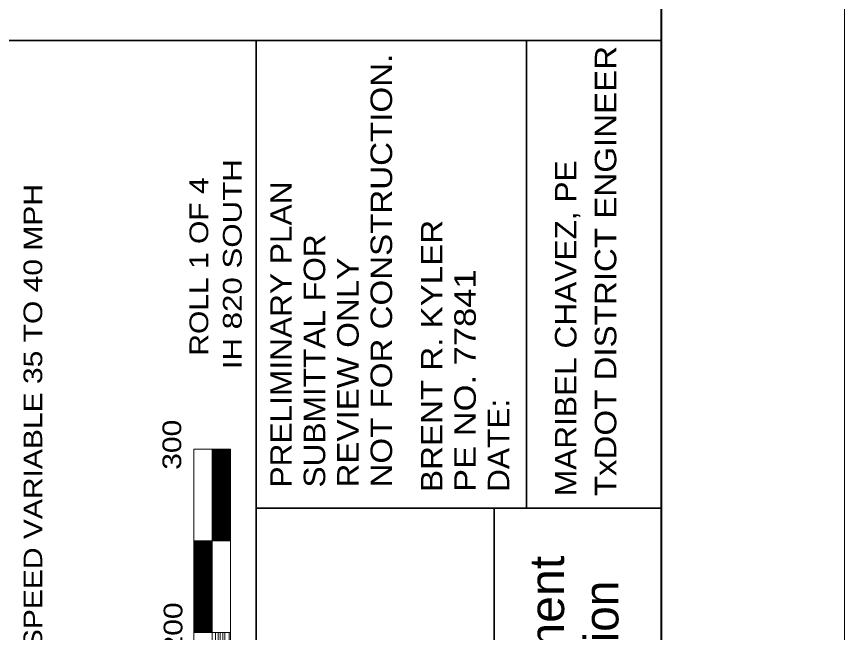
# Model space of a CAD drawing. Extents: x 2363323 to 2367082, y 6956018 to 6980837.
# Drawn here: x 2366471.6 to 2366923.3, y 6957628.9 to 6957965 of the extents above; entities that cross this region are included whole.
import ezdxf
from ezdxf.enums import TextEntityAlignment as Align

# ---------------------------------------------------------------- set-up
doc = ezdxf.new("R2010")
doc.units = 0
doc.header["$LTSCALE"] = 4.1
doc.layers.add('62', color=7, linetype='Continuous', lineweight=13)
doc.layers.add('63', color=7, linetype='Continuous', lineweight=13)

msp = doc.modelspace()

# ---------------------------------------------------------------- linework, layer by layer
at = {"layer": '62'}
for p, q in [((2366923.344, 6980256.082), (2366923.344, 6957200.912)), ((2366568.268, 6957328.893), (2366568.268, 6957728.93)), ((2366568.268, 6957728.93), (2366578.269, 6957728.93)), ((2366578.269, 6957328.894), (2366578.269, 6957728.93)), ((2366578.269, 6957728.93), (2366588.27, 6957728.93)), ((2366578.536, 6957678.925), (2366578.537, 6957728.929)), ((2366579.036, 6957678.925), (2366579.036, 6957728.929)), ((2366579.536, 6957678.924), (2366579.536, 6957728.93)), ((2366580.036, 6957678.924), (2366580.037, 6957728.929)), ((2366580.535, 6957678.924), (2366580.536, 6957728.929)), ((2366581.036, 6957678.924), (2366581.036, 6957728.929)), ((2366581.536, 6957678.924), (2366581.535, 6957728.929)), ((2366582.036, 6957678.924), (2366582.035, 6957728.93)), ((2366582.536, 6957678.925), (2366582.536, 6957728.929)), ((2366583.036, 6957678.925), (2366583.035, 6957728.929)), ((2366583.536, 6957678.925), (2366583.536, 6957728.93)), ((2366584.036, 6957678.925), (2366584.036, 6957728.93)), ((2366584.536, 6957678.923), (2366584.536, 6957728.93)), ((2366585.036, 6957678.924), (2366585.036, 6957728.929)), ((2366585.537, 6957678.924), (2366585.536, 6957728.929)), ((2366586.037, 6957678.924), (2366586.037, 6957728.929)), ((2366586.537, 6957678.924), (2366586.537, 6957728.929)), ((2366587.037, 6957678.924), (2366587.037, 6957728.93)), ((2366587.537, 6957678.925), (2366587.537, 6957728.929)), ((2366588.037, 6957678.925), (2366588.037, 6957728.93)), ((2366588.269, 6957328.893), (2366588.27, 6957728.93)), ((2366568.268, 6957678.924), (2366578.268, 6957678.924)), ((2366568.659, 6957628.921), (2366568.659, 6957678.924)), ((2366569.16, 6957628.921), (2366569.16, 6957678.925)), ((2366569.66, 6957628.921), (2366569.66, 6957678.924)), ((2366570.159, 6957628.92), (2366570.16, 6957678.925)), ((2366570.659, 6957628.92), (2366570.661, 6957678.924)), ((2366571.16, 6957628.92), (2366571.16, 6957678.924)), ((2366571.66, 6957628.921), (2366571.66, 6957678.925)), ((2366572.16, 6957628.92), (2366572.16, 6957678.924)), ((2366572.66, 6957628.92), (2366572.66, 6957678.924)), ((2366573.16, 6957628.921), (2366573.161, 6957678.924)), ((2366573.66, 6957628.92), (2366573.661, 6957678.925)), ((2366574.16, 6957628.921), (2366574.16, 6957678.925)), ((2366574.66, 6957628.92), (2366574.66, 6957678.924)), ((2366575.16, 6957628.921), (2366575.159, 6957678.924)), ((2366575.66, 6957628.92), (2366575.66, 6957678.924)), ((2366576.16, 6957628.92), (2366576.16, 6957678.925)), ((2366576.66, 6957628.921), (2366576.659, 6957678.925)), ((2366577.16, 6957628.92), (2366577.16, 6957678.924)), ((2366577.66, 6957628.921), (2366577.66, 6957678.925)), ((2366578.16, 6957628.921), (2366578.16, 6957678.924)), ((2366578.268, 6957678.924), (2366588.27, 6957678.924)), ((2366568.268, 6957628.921), (2366578.269, 6957628.921)), ((2366578.269, 6957628.921), (2366588.269, 6957628.92)), ((2366580.16, 6957578.915), (2366580.16, 6957628.921)), ((2366581.66, 6957578.915), (2366581.659, 6957628.921)), ((2366582.66, 6957578.915), (2366582.659, 6957628.921)), ((2366584.16, 6957578.916), (2366584.159, 6957628.921)), ((2366585.162, 6957578.916), (2366585.161, 6957628.921)), ((2366587.661, 6957578.916), (2366587.661, 6957628.921))]:
    msp.add_line(p, q, dxfattribs=at)
at = {"layer": '62', "lineweight": 40}
msp.add_line((2366823.34, 6980156.078), (2366823.34, 6957300.912), dxfattribs=at)
at = {"layer": '62', "lineweight": 35}
for p, q in [((2366226.481, 6957951.933), (2366823.339, 6957951.933)), ((2366602.353, 6957951.933), (2366602.354, 6957300.911)), ((2366749.892, 6957951.933), (2366749.892, 6957696.747)), ((2366823.338, 6957696.748), (2366602.353, 6957696.746)), ((2366732.124, 6957696.747), (2366732.124, 6957300.911))]:
    msp.add_line(p, q, dxfattribs=at)
at = {"layer": '62'}
for points in [[(2366588.27, 6957678.924), (2366588.27, 6957728.93), (2366578.269, 6957728.93), (2366578.268, 6957678.924)], [(2366578.269, 6957628.921), (2366578.268, 6957678.924), (2366568.268, 6957678.924), (2366568.268, 6957628.921)], [(2366588.27, 6957578.915), (2366588.269, 6957628.92), (2366578.269, 6957628.921), (2366578.269, 6957578.915)]]:
    msp.add_lwpolyline(points, close=True, dxfattribs=at)
at = {"layer": '63'}
for p, q in [((2366923.344, 6980256.082), (2366923.344, 6957200.912)), ((2366568.268, 6957328.893), (2366568.268, 6957728.93)), ((2366568.268, 6957728.93), (2366578.269, 6957728.93)), ((2366578.269, 6957328.894), (2366578.269, 6957728.93)), ((2366578.269, 6957728.93), (2366588.27, 6957728.93)), ((2366578.536, 6957678.925), (2366578.537, 6957728.929)), ((2366579.036, 6957678.925), (2366579.036, 6957728.929)), ((2366579.536, 6957678.924), (2366579.536, 6957728.93)), ((2366580.036, 6957678.924), (2366580.037, 6957728.929)), ((2366580.535, 6957678.924), (2366580.536, 6957728.929)), ((2366581.036, 6957678.924), (2366581.036, 6957728.929)), ((2366581.536, 6957678.924), (2366581.535, 6957728.929)), ((2366582.036, 6957678.924), (2366582.035, 6957728.93)), ((2366582.536, 6957678.925), (2366582.536, 6957728.929)), ((2366583.036, 6957678.925), (2366583.035, 6957728.929)), ((2366583.536, 6957678.925), (2366583.536, 6957728.93)), ((2366584.036, 6957678.925), (2366584.036, 6957728.93)), ((2366584.536, 6957678.923), (2366584.536, 6957728.93)), ((2366585.036, 6957678.924), (2366585.036, 6957728.929)), ((2366585.537, 6957678.924), (2366585.536, 6957728.929)), ((2366586.037, 6957678.924), (2366586.037, 6957728.929)), ((2366586.537, 6957678.924), (2366586.537, 6957728.929)), ((2366587.037, 6957678.924), (2366587.037, 6957728.93)), ((2366587.537, 6957678.925), (2366587.537, 6957728.929)), ((2366588.037, 6957678.925), (2366588.037, 6957728.93)), ((2366588.269, 6957328.893), (2366588.27, 6957728.93)), ((2366568.268, 6957678.924), (2366578.268, 6957678.924)), ((2366568.659, 6957628.921), (2366568.659, 6957678.924)), ((2366569.16, 6957628.921), (2366569.16, 6957678.925)), ((2366569.66, 6957628.921), (2366569.66, 6957678.924)), ((2366570.159, 6957628.92), (2366570.16, 6957678.925)), ((2366570.659, 6957628.92), (2366570.661, 6957678.924)), ((2366571.16, 6957628.92), (2366571.16, 6957678.924)), ((2366571.66, 6957628.921), (2366571.66, 6957678.925)), ((2366572.16, 6957628.92), (2366572.16, 6957678.924)), ((2366572.66, 6957628.92), (2366572.66, 6957678.924)), ((2366573.16, 6957628.921), (2366573.161, 6957678.924)), ((2366573.66, 6957628.92), (2366573.661, 6957678.925)), ((2366574.16, 6957628.921), (2366574.16, 6957678.925)), ((2366574.66, 6957628.92), (2366574.66, 6957678.924)), ((2366575.16, 6957628.921), (2366575.159, 6957678.924)), ((2366575.66, 6957628.92), (2366575.66, 6957678.924)), ((2366576.16, 6957628.92), (2366576.16, 6957678.925)), ((2366576.66, 6957628.921), (2366576.659, 6957678.925)), ((2366577.16, 6957628.92), (2366577.16, 6957678.924)), ((2366577.66, 6957628.921), (2366577.66, 6957678.925)), ((2366578.16, 6957628.921), (2366578.16, 6957678.924)), ((2366578.268, 6957678.924), (2366588.27, 6957678.924)), ((2366568.268, 6957628.921), (2366578.269, 6957628.921)), ((2366578.269, 6957628.921), (2366588.269, 6957628.92)), ((2366580.16, 6957578.915), (2366580.16, 6957628.921)), ((2366581.66, 6957578.915), (2366581.659, 6957628.921)), ((2366582.66, 6957578.915), (2366582.659, 6957628.921)), ((2366584.16, 6957578.916), (2366584.159, 6957628.921)), ((2366585.162, 6957578.916), (2366585.161, 6957628.921)), ((2366587.661, 6957578.916), (2366587.661, 6957628.921))]:
    msp.add_line(p, q, dxfattribs=at)
at = {"layer": '63', "lineweight": 40}
msp.add_line((2366823.34, 6980156.078), (2366823.34, 6957300.912), dxfattribs=at)
at = {"layer": '63', "lineweight": 35}
for p, q in [((2366226.481, 6957951.933), (2366823.339, 6957951.933)), ((2366602.353, 6957951.933), (2366602.354, 6957300.911)), ((2366749.892, 6957951.933), (2366749.892, 6957696.316)), ((2366823.338, 6957696.748), (2366602.353, 6957696.746))]:
    msp.add_line(p, q, dxfattribs=at)
at = {"layer": '63'}
for points in [[(2366588.27, 6957678.924), (2366588.27, 6957728.93), (2366578.269, 6957728.93), (2366578.268, 6957678.924)], [(2366578.269, 6957628.921), (2366578.268, 6957678.924), (2366568.268, 6957678.924), (2366568.268, 6957628.921)], [(2366588.27, 6957578.915), (2366588.269, 6957628.92), (2366578.269, 6957628.921), (2366578.269, 6957578.915)]]:
    msp.add_lwpolyline(points, close=True, dxfattribs=at)

# ---------------------------------------------------------------- texts
at = {"layer": '62'}
for s, width, p in [('TxDOT DISTRICT ENGINEER', 1.15, (2366798.864, 6957703.252)), ('NOT FOR CONSTRUCTION.', 1.15, (2366676.499, 6957708.016)), ('MARIBEL CHAVEZ, PE', 1.1, (2366777.125, 6957703.251)), ('PRELIMINARY PLAN', 1.1, (2366621.773, 6957708.015)), ('BRENT R. KYLER', 1.15, (2366703.962, 6957705.575)), ('SUBMITTAL FOR', 1.1, (2366640.015, 6957708.016)), ('REVIEW ONLY', 1.15, (2366658.257, 6957708.016)), ('PE NO. 77841', 1.2, (2366722.199, 6957705.575)), ('DATE: ', 1.1, (2366740.434, 6957705.576))]:
    msp.add_text(s, height=11.74, rotation=90, dxfattribs=dict(at, width=width)).set_placement(p)
for s, height, width, p in [('IH 820 SOUTH', 10.2, 1.25, (2366594.414, 6957829.863)), ('ROLL 1 OF 4', 10.2, 1.2, (2366576.159, 6957828.614)), ('FRONTAGE ROAD DESIGN SPEED VARIABLE 35 TO 40 MPH', 10.2, 1.2, (2366485.591, 6957639.41)), ('300', 10.2, 1.2, (2366561.427, 6957731.346)), ('Texas Department', 18.76, 1.05, (2366770.36, 6957562.432)), ('200', 10.2, 1.2, (2366562.077, 6957631.661))]:
    msp.add_text(s, height=height, rotation=90, dxfattribs=dict(at, width=width)).set_placement(p, align=Align.CENTER)
msp.add_text('of Transportation', height=18.76, rotation=90, dxfattribs=at).set_placement((2366800.012, 6957562.362), align=Align.CENTER)
at = {"layer": '63'}
for s, width, p in [('NOT FOR CONSTRUCTION.', 1.15, (2366676.499, 6957708.016)), ('PRELIMINARY PLAN', 1.1, (2366621.773, 6957708.015)), ('SUBMITTAL FOR', 1.1, (2366640.015, 6957708.016)), ('REVIEW ONLY', 1.15, (2366658.257, 6957708.016))]:
    msp.add_text(s, height=11.74, rotation=90, dxfattribs=dict(at, width=width)).set_placement(p)
for s, height, width, p in [('IH 820 SOUTH', 10.2, 1.25, (2366594.414, 6957829.863)), ('300', 10.2, 1.2, (2366561.427, 6957731.346)), ('Texas Department', 18.76, 1.05, (2366770.36, 6957562.432)), ('200', 10.2, 1.2, (2366562.077, 6957631.661))]:
    msp.add_text(s, height=height, rotation=90, dxfattribs=dict(at, width=width)).set_placement(p, align=Align.CENTER)
msp.add_text('of Transportation', height=18.76, rotation=90, dxfattribs=at).set_placement((2366800.012, 6957562.362), align=Align.CENTER)

doc.saveas('drawing.dxf')
